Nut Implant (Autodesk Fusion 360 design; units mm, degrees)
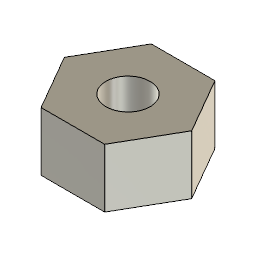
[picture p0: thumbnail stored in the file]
part number: 2025-09-29-22-40-45-153
sketch "Sketch1" plane through (0, 0, 0) normal (0, 0, 1) x axis (1, 0, 0)
  line L1 (-3.25, 5.6292) -> (3.25, 5.6292)
  line L2 (-6.5, 0) -> (-3.25, 5.6292)
  line L3 (-3.25, -5.6292) -> (-6.5, 0)
  line L4 (3.25, -5.6292) -> (-3.25, -5.6292)
  line L5 (6.5, 0) -> (3.25, -5.6292)
  line L6 (3.25, 5.6292) -> (6.5, 0)
  point P1 (0, 0)
  point P8 (0, 0)
  point P7 (6.5, 0)
  coincident P1 P8
  horizontal L1
  dimension "d8" distance P7 P8 = 6.5
extrude "Extrude1" new body sketch "Sketch1" along normal blind 6
sketch "Sketch2" plane through (0, 0, 6) normal (0, 0, 1) x axis (-1, 0, 0)
  line L1 (-3.25, -5.6292) -> (-6.5, 0)
  line L2 (3.25, -5.6292) -> (-3.25, -5.6292)
  line L3 (6.5, 0) -> (3.25, -5.6292)
  line L4 (3.25, 5.6292) -> (6.5, 0)
  line L5 (-3.25, 5.6292) -> (3.25, 5.6292)
  line L6 (-6.5, 0) -> (-3.25, 5.6292)
  circle C1 centre (0, 0) radius 2.25
  point P1 (0, 0)
  point P8 (0, 0)
  coincident P1 P8
  dimension "d5" diameter C1 = 4.5
extrude "Extrude2" cut sketch "Sketch2" profile of C1 against normal blind 6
